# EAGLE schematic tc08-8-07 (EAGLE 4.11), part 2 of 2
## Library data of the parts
A02-A06 D02-D06 = dec-m:M903: Two-sided Posibus cable/connector.
A07 D07 = dec-m:M161: Octal or Decimal Decoder
A08 B09 B13 B14 C09 C14 D11 = dec-m:M206X: Two sets of 3 D flip-flops
A09 B12 = dec-m:M117: 6 4-input NAND Gates
A10 A12 B08 B15 C11 C15 = dec-m:M113: 10 2-input NAND Gates
A11 B06 C06 C13 C17 = dec-m:M111: Sixteen inverters.
A13 A17 A27 A28 B17 B24-B28 C19-C28 D01 D19-D28 = dec-m:H807: Empty card slot
A14 D16 = dec-m:M302: Dual one-shot
A15 B10 C16 D12 = dec-m:M627: 6 4-input NAND Power Amplifier
A16 B16 D13 D17 = dec-m:M602: Dual Pulse Amplifier
A18 A20 A21 B18 B20 = dec-m:G888: Manchester Reader/Writer
A22 = dec-m:M502: Dual Negative Input Converter
A23 B22 = dec-m:M633: 6 Dual Negative Bus Drivers
A24 = dec-m:W023: One-sided 18 pin connector/cable.
A25 A26 = dec-m:M916: Simple 36 pin connector/wire cable
AB01 = dec-m:G821: +5V Regulator
AB19 = dec-m:W032: Cable Connector (15 signals)
B02-B05 = dec-m:M623: 6 Dual Bus Drivers
B07 C07 D08 = dec-m:M207: 6 J-K flip-flops
B11 C12 = dec-m:M115: 8 3-input NAND Gates
B21 = dec-m:G879: Transport Detector
B23 = dec-m:W005: 15 Clamped Loads
C01 = dec-m:M101: Bus Data Interface The M101 contains 15 two-input NAND gates. One input of each gate is tied to a common line so that all data signals can be enabled simultaneously. Each data signal presents one TTL load. The common input presents 15 loads. Each output can drive 10 loads. Power: 5V@82ma (max.)
C02 C03 = dec-m:M101-ARRAY: M101 Bus Data Interface
C04 C05 = dec-m:M103: M103 Device Selector Used to decode IOT requests.
C08 C10 D09 = dec-m:M121: 6 2-2 AND-NOR Gates
CD18 = dec-m:M228: Mark Track Decoder
D10 = dec-m:M119: 3 8-input NAND Gates
D14 = dec-m:M307: Dual Integrating One-Shot
D15 = dec-m:M401: Variable Clock

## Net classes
1 Power: width 0.635 mm, drill 0.381 mm, clearance 0.381 mm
